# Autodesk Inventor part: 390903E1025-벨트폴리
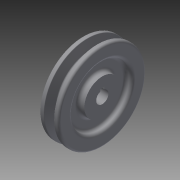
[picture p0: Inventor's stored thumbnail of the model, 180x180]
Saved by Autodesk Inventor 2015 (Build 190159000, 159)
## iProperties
Created: 2019-09
Part Number: 390903E1025-벨트폴리
Material: 일반
Document SubType Name: Modeling
Designer: now
Density: 1 g/cm^3
Appearance: 기본값
Mass: 73.3597 g
Surface Area: 224.091 cm^2
Volume: 73.3597 cm^3
Author: now
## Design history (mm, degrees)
sketch "스케치1"
  geometry: C1 r 42.5 at (0, 0); 1 further point
  constraints: 1 centre point, 1 coincident
  dimensions: "d0" = 85 diameter of C1
extrude "돌출1" new body sketch "스케치1" stored distance "d1" = 19; taper "d2" = 0 deg
sketch "스케치2"
  geometry: C1 r 42.5 at (0, 0) reference; C2 r 17.5 at (0, 0)
  constraints: 1 centre point, 1 coincident
  dimensions: "d3" = 35 diameter of C2
extrude "돌출2" join sketch "스케치2" distance "d4" = 5; taper "d5" = 0 deg
sketch "스케치3"
  geometry: L1 (9.5, 17.5)-(14.5, 17.5) reference; L2 (14.5, 17.5)-(14.5, -17.5) reference; L3 (14.5, -17.5)-(9.5, -17.5) reference; L4 (9.5, -17.5)-(9.5, -42.5) reference; L5 (9.5, -42.5)-(-9.5, -42.5) reference; L6 (-9.5, -42.5)-(-9.5, 42.5) reference; L7 (-9.5, 42.5)-(9.5, 42.5) reference; L8 (9.5, 42.5)-(9.5, 17.5) reference; L9 (4.877, 42.5)-(1.953, 33.5); L10 (1.953, 33.5)-(-1.953, 33.5); L11 (-1.953, 33.5)-(-4.877, 42.5); L12 (0, 42.5)-(0, 33.5); L13 (4, 39.8)-(-4, 39.8); L14 (19.3, 0)-(-14.3, 0) reference; 1 further point
  constraints: 10 end point, 4 point on line, 2 horizontal, 2 midpoint, 1 vertical, 1 other
  dimensions: "d30" = 36 deg angle of L11 L9; "d31" = 2.7 distance between parallel lines of L13 L7; "d32" = 6.3 distance between parallel lines of L10 L13; "d33" = 8 distance of L13.start L13.end
revolve "회전1" sketch "스케치3" stored, may be unused: angle "d10" = 90 deg
sketch "스케치4"
  geometry: C1 r 42.5 at (0, 0) reference
hole "구멍1" sketch "스케치4" at (0, 0) diameter "d11" = 12; stored, may be unused: countersink angle "d15" = 90 deg, drill point angle "d17" = 118 deg; dims "d12" = 6, "d13" = 4, "d14" = 2, "d16" = 8
sketch "스케치5"
  geometry: L1 (-7.8, -2)-(0, -2); L2 (0, -2)-(0, 2); L3 (0, 2)-(-7.8, 2); L4 (-7.8, 2)-(-7.8, -2); C1 r 6 at (0, 0) reference; 1 further point
  constraints: 8 end point, 2 coincident, 2 parallel, 1 horizontal, 1 midpoint, 1 perpendicular
  dimensions: "d18" = 4 distance of L3.end L1.start; "d19" = 7.8 distance from line of C1.centre L4
extrude "돌출3" cut sketch "스케치5" distance "d20" = 25; taper "d21" = 0 deg
sketch "스케치6"
  geometry: C1 r 17.5 at (0, 0) reference; C2 r 42.5 at (0, 0) reference; C3 r 29 at (0, 0); C4 r 17.5 at (0, 0)
  constraints: 2 centre point, 2 coincident
  dimensions: "d22" = 58 diameter of C3; "d23" = 35 diameter of C4
extrude "돌출4" cut sketch "스케치6" distance "d24" = 6; taper "d25" = 0 deg
fillet "모깎기1" dims "d26" = 1
fillet "모깎기2" dims "d27" = 0.5
fillet "모깎기3" dims "d28" = 2
fillet "모깎기4" dims "d29" = 3
node "솔리드1"
mirror "대칭1"
node "절단 모서리 투영1"
